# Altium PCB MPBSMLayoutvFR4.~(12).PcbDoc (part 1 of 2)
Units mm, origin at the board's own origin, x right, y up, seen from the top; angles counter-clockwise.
Board outline 131.7 x 110.39 mm, 4 copper layers (Top Layer, Power, GroundPlane, Bottom Layer), stack 2.286 mm thick; 156 components, 77 nets, 429 pads, 117 vias.
Unrouted connection lines stored in the file: 25.
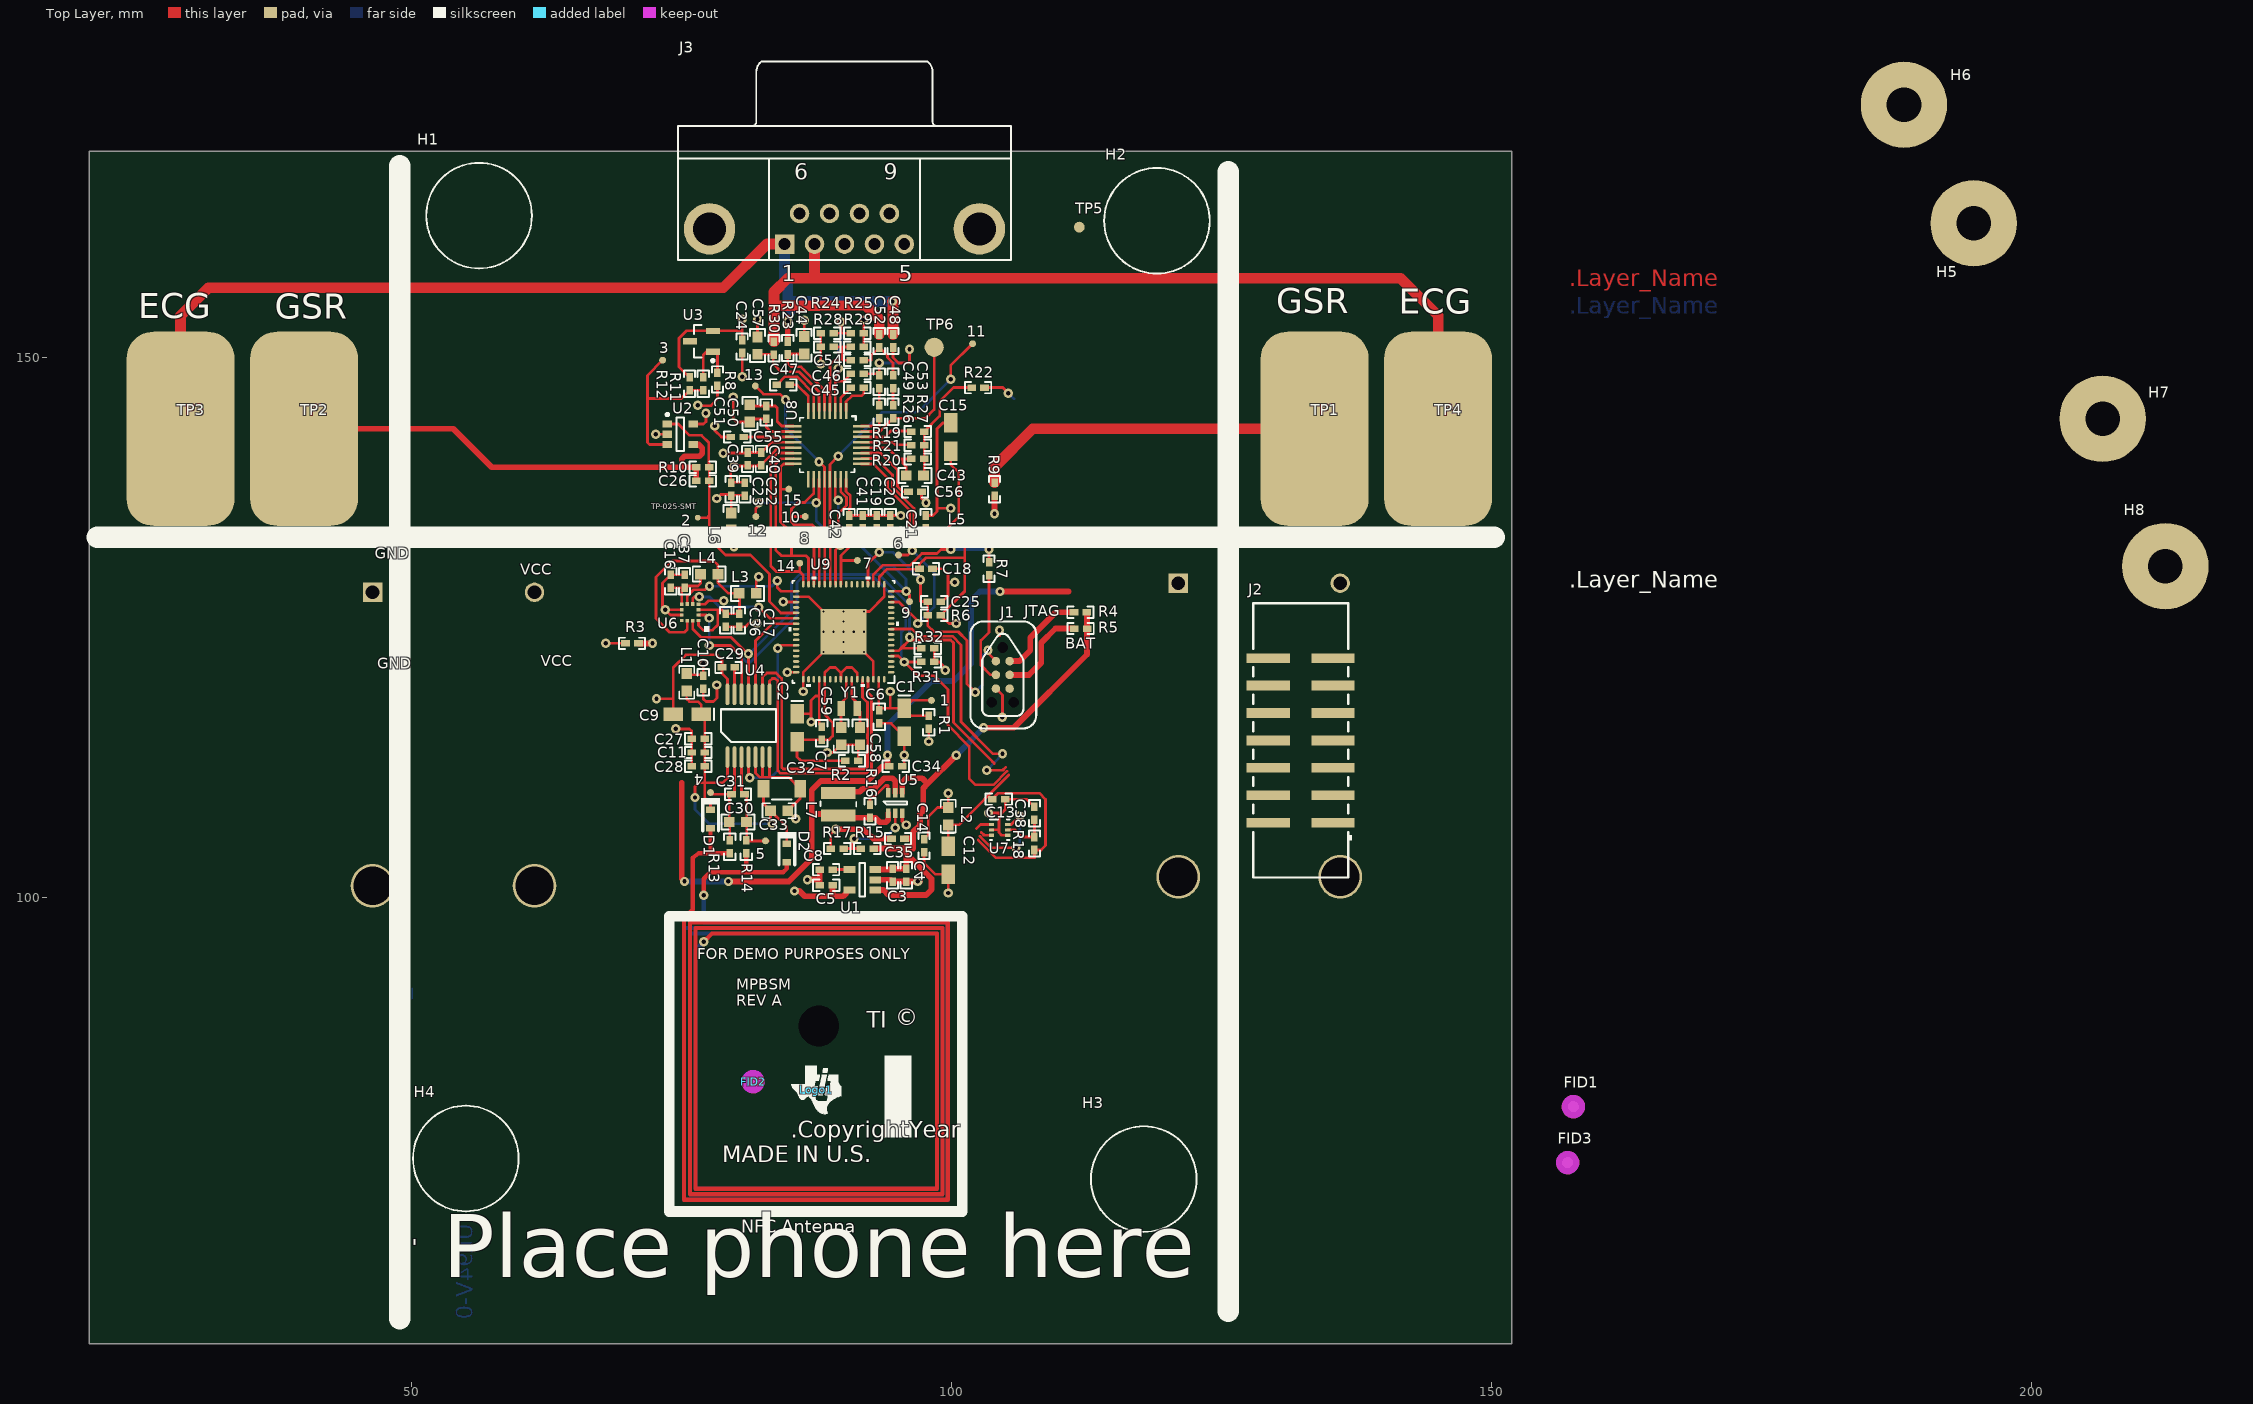
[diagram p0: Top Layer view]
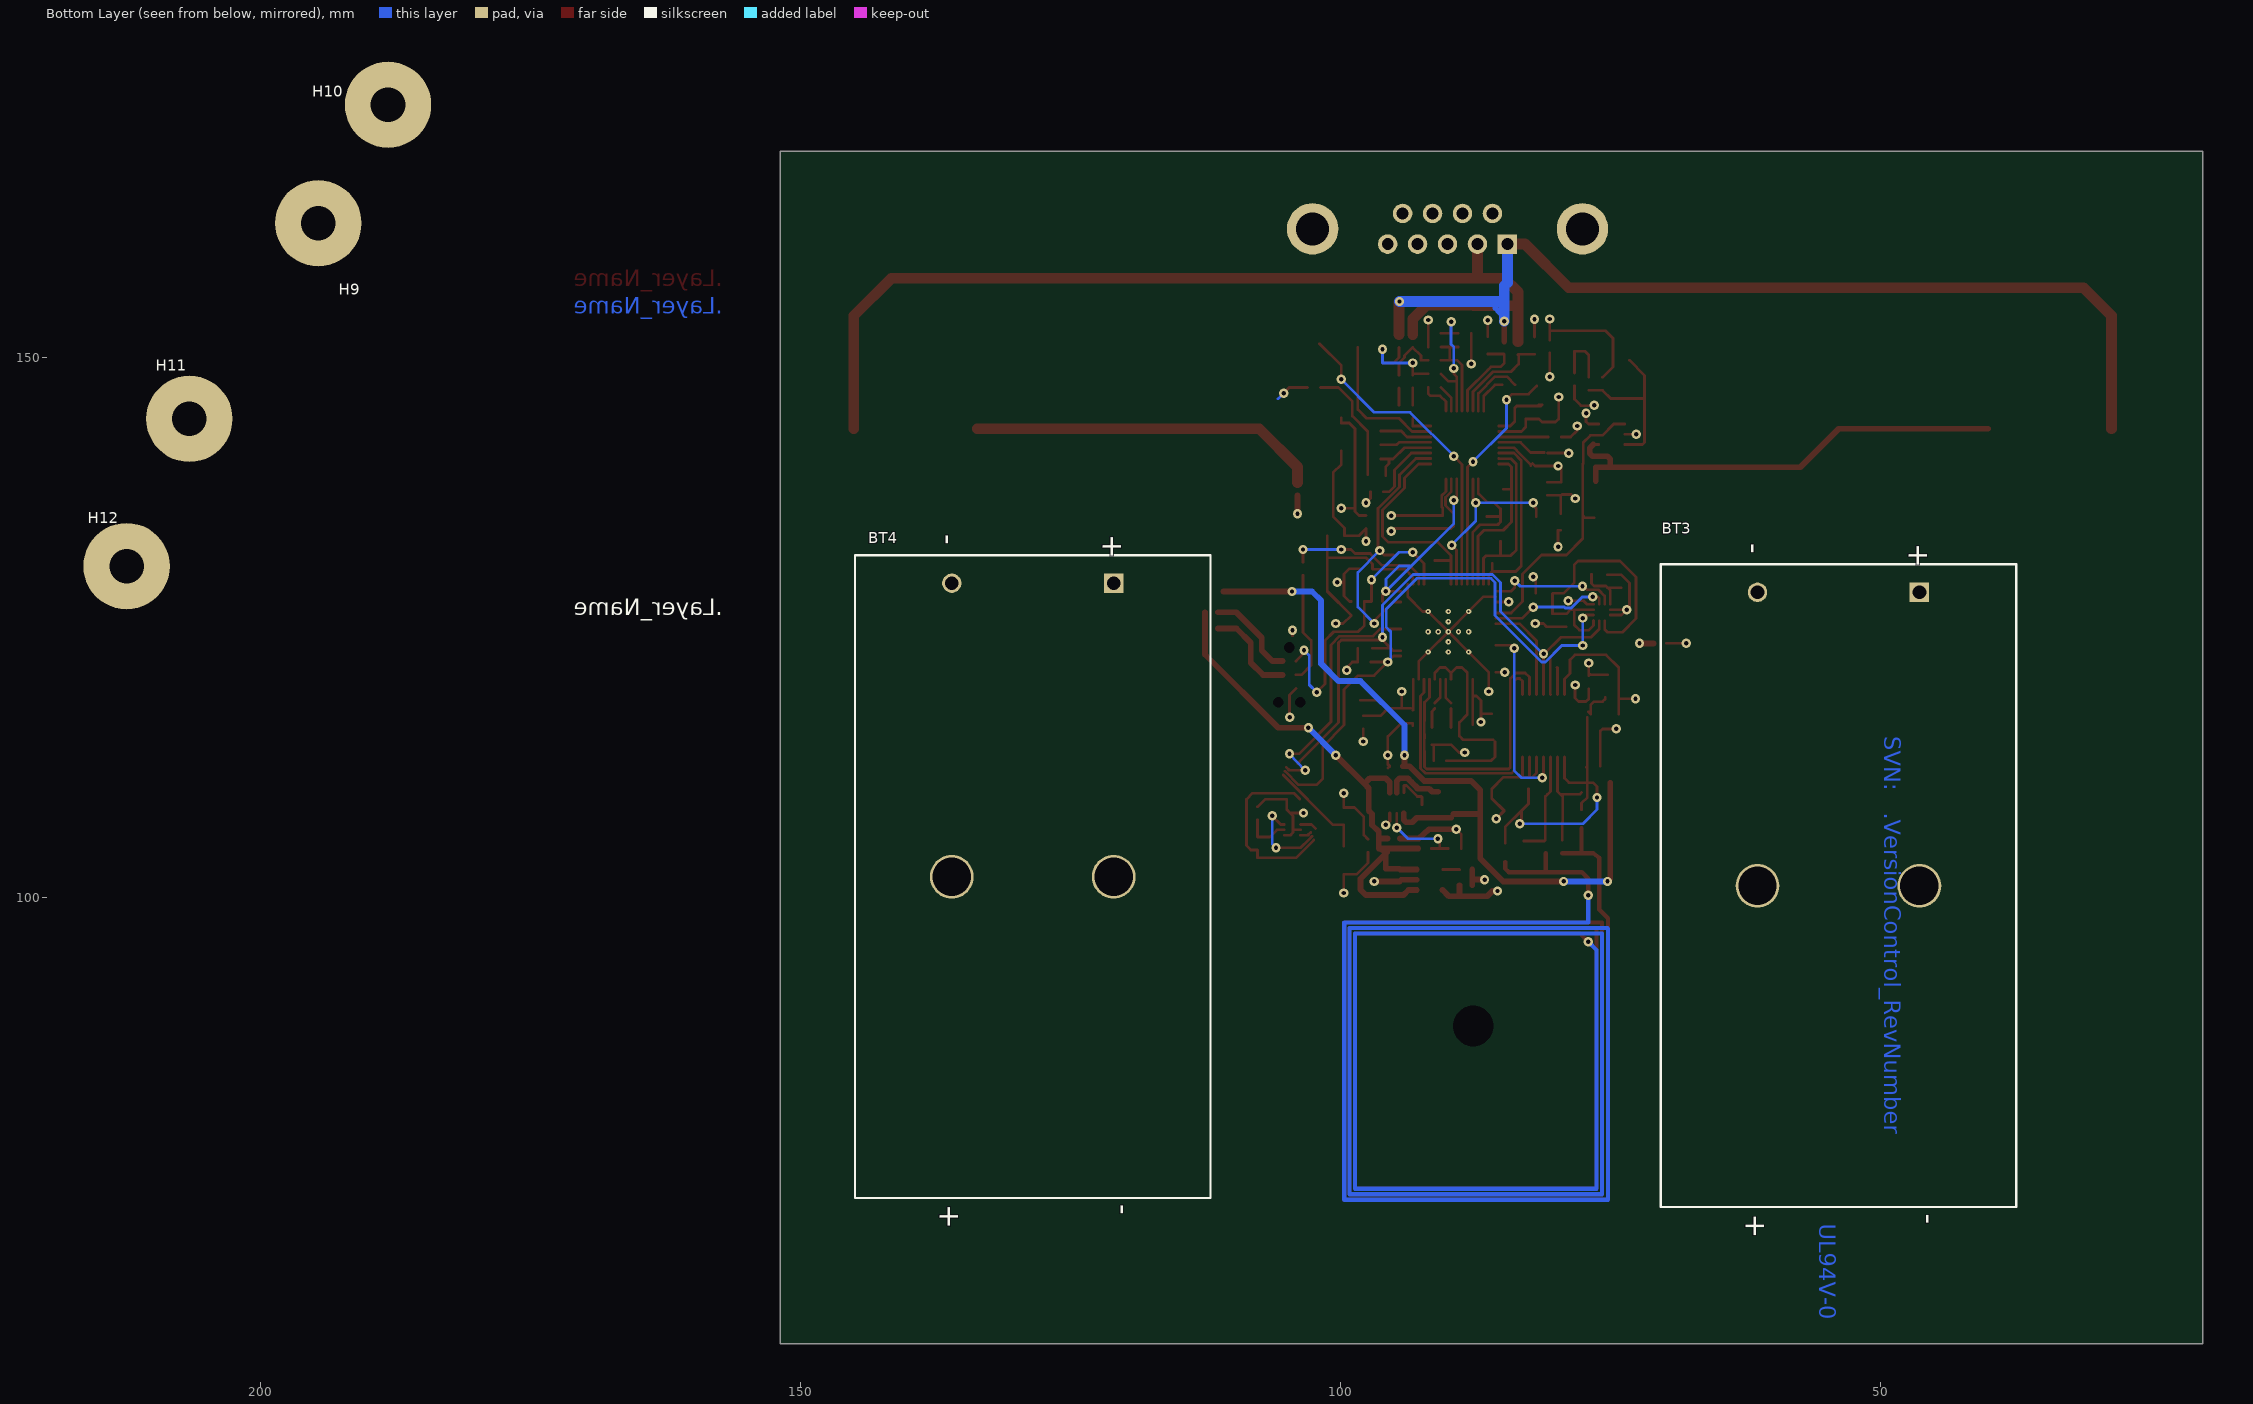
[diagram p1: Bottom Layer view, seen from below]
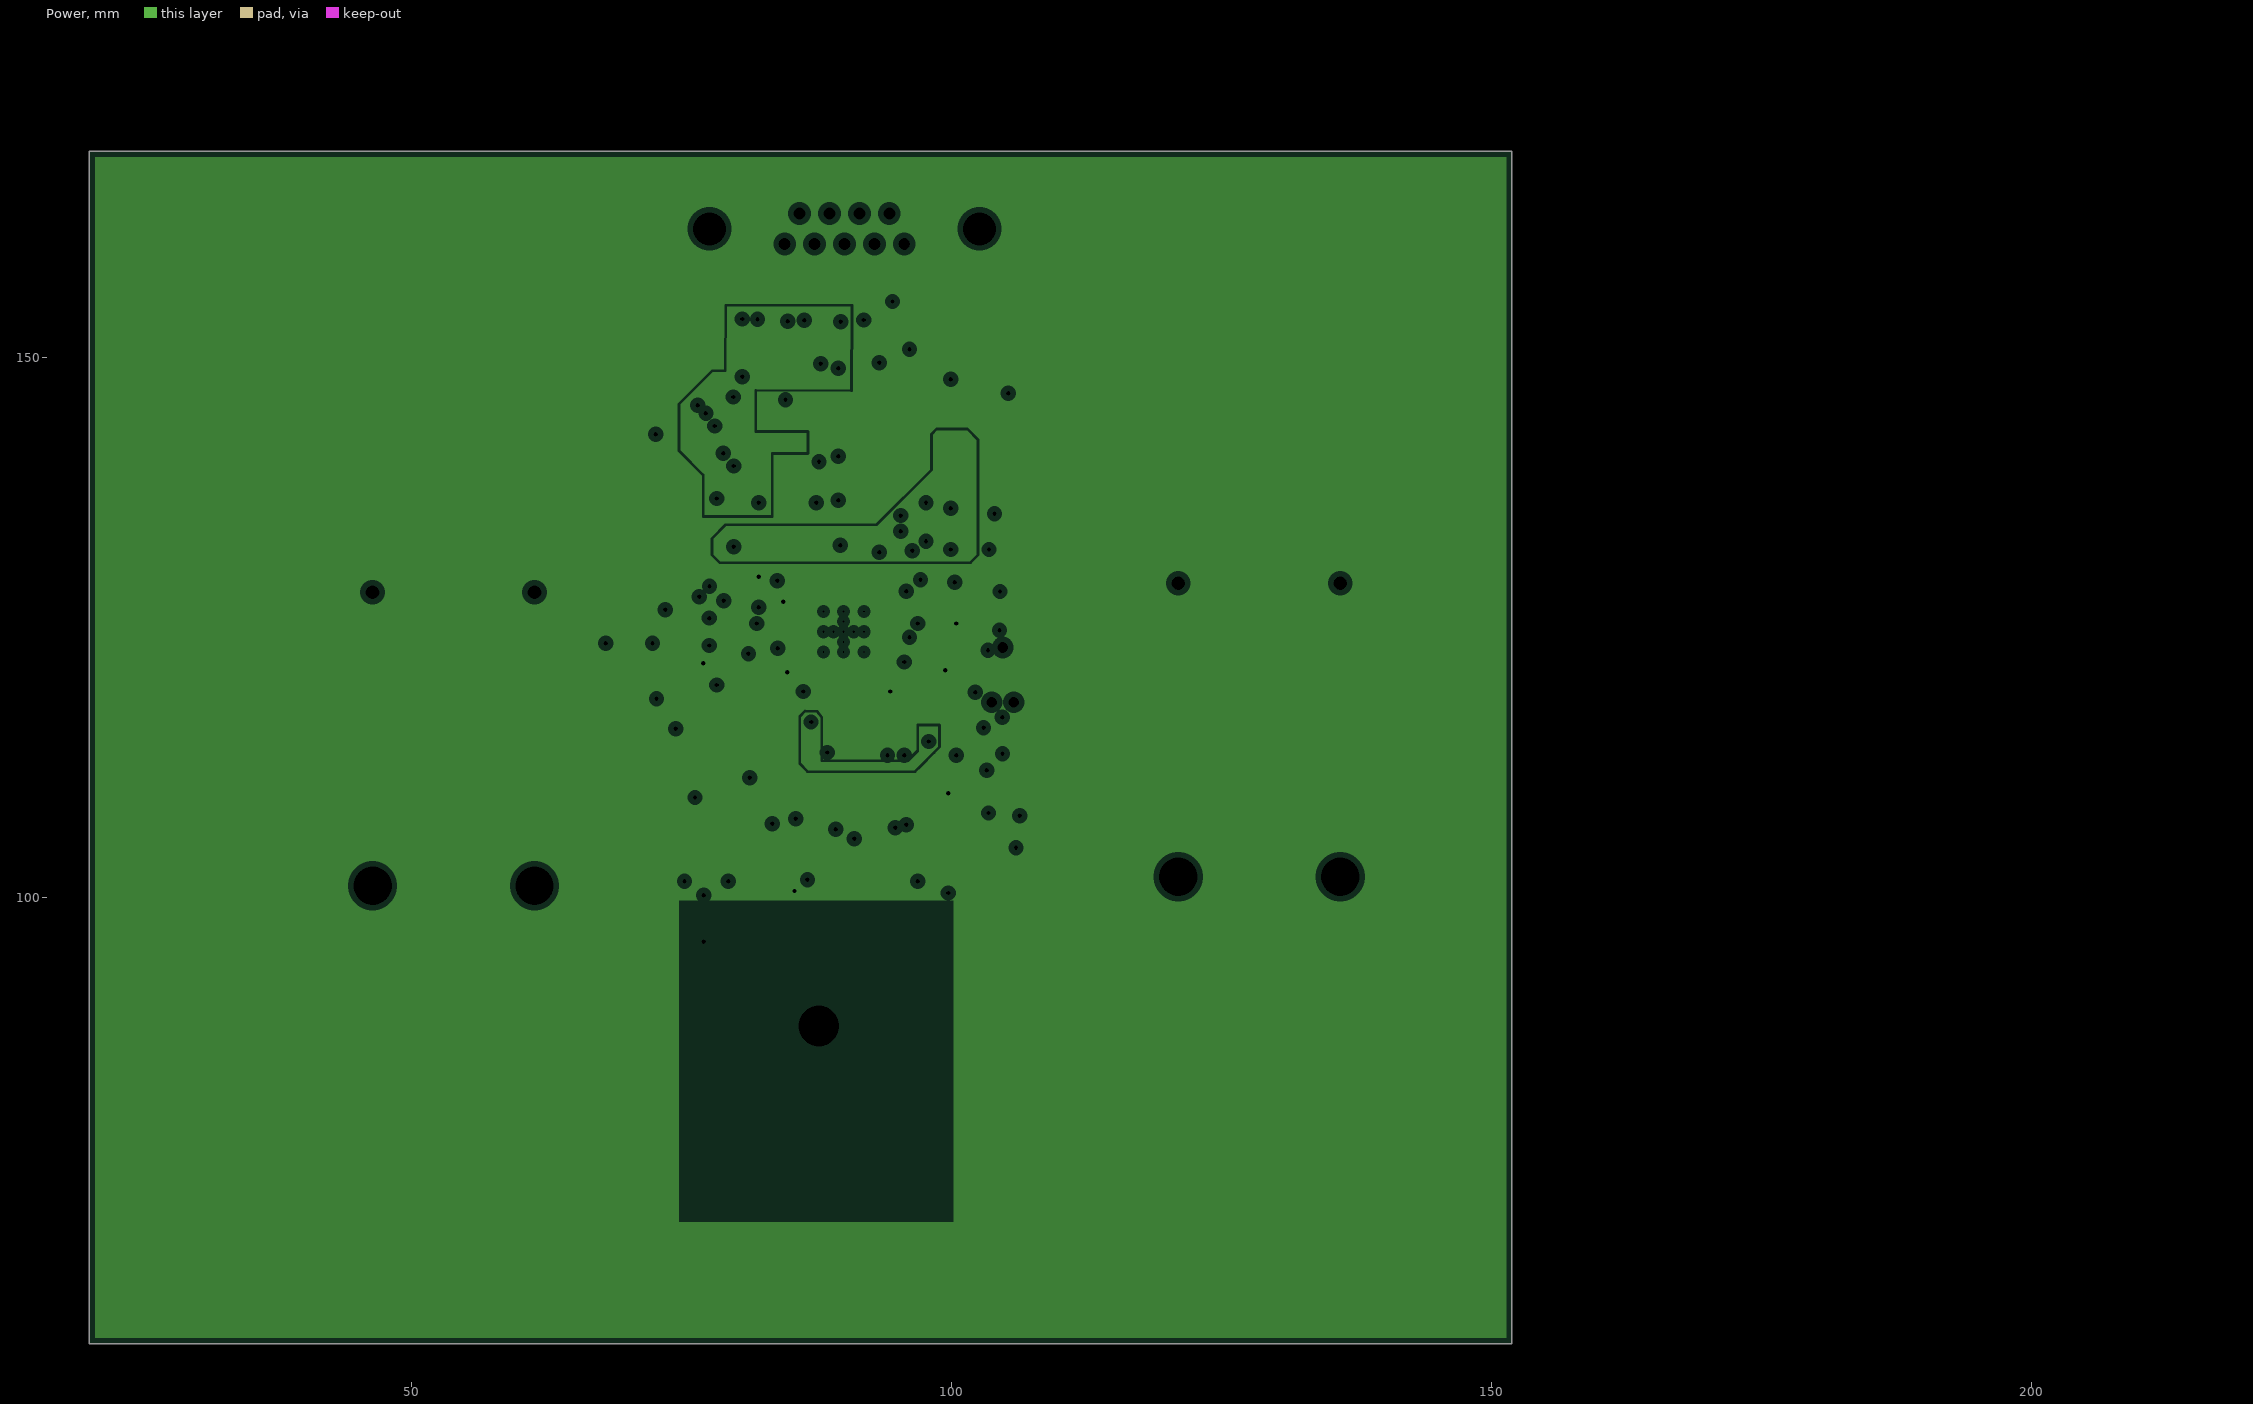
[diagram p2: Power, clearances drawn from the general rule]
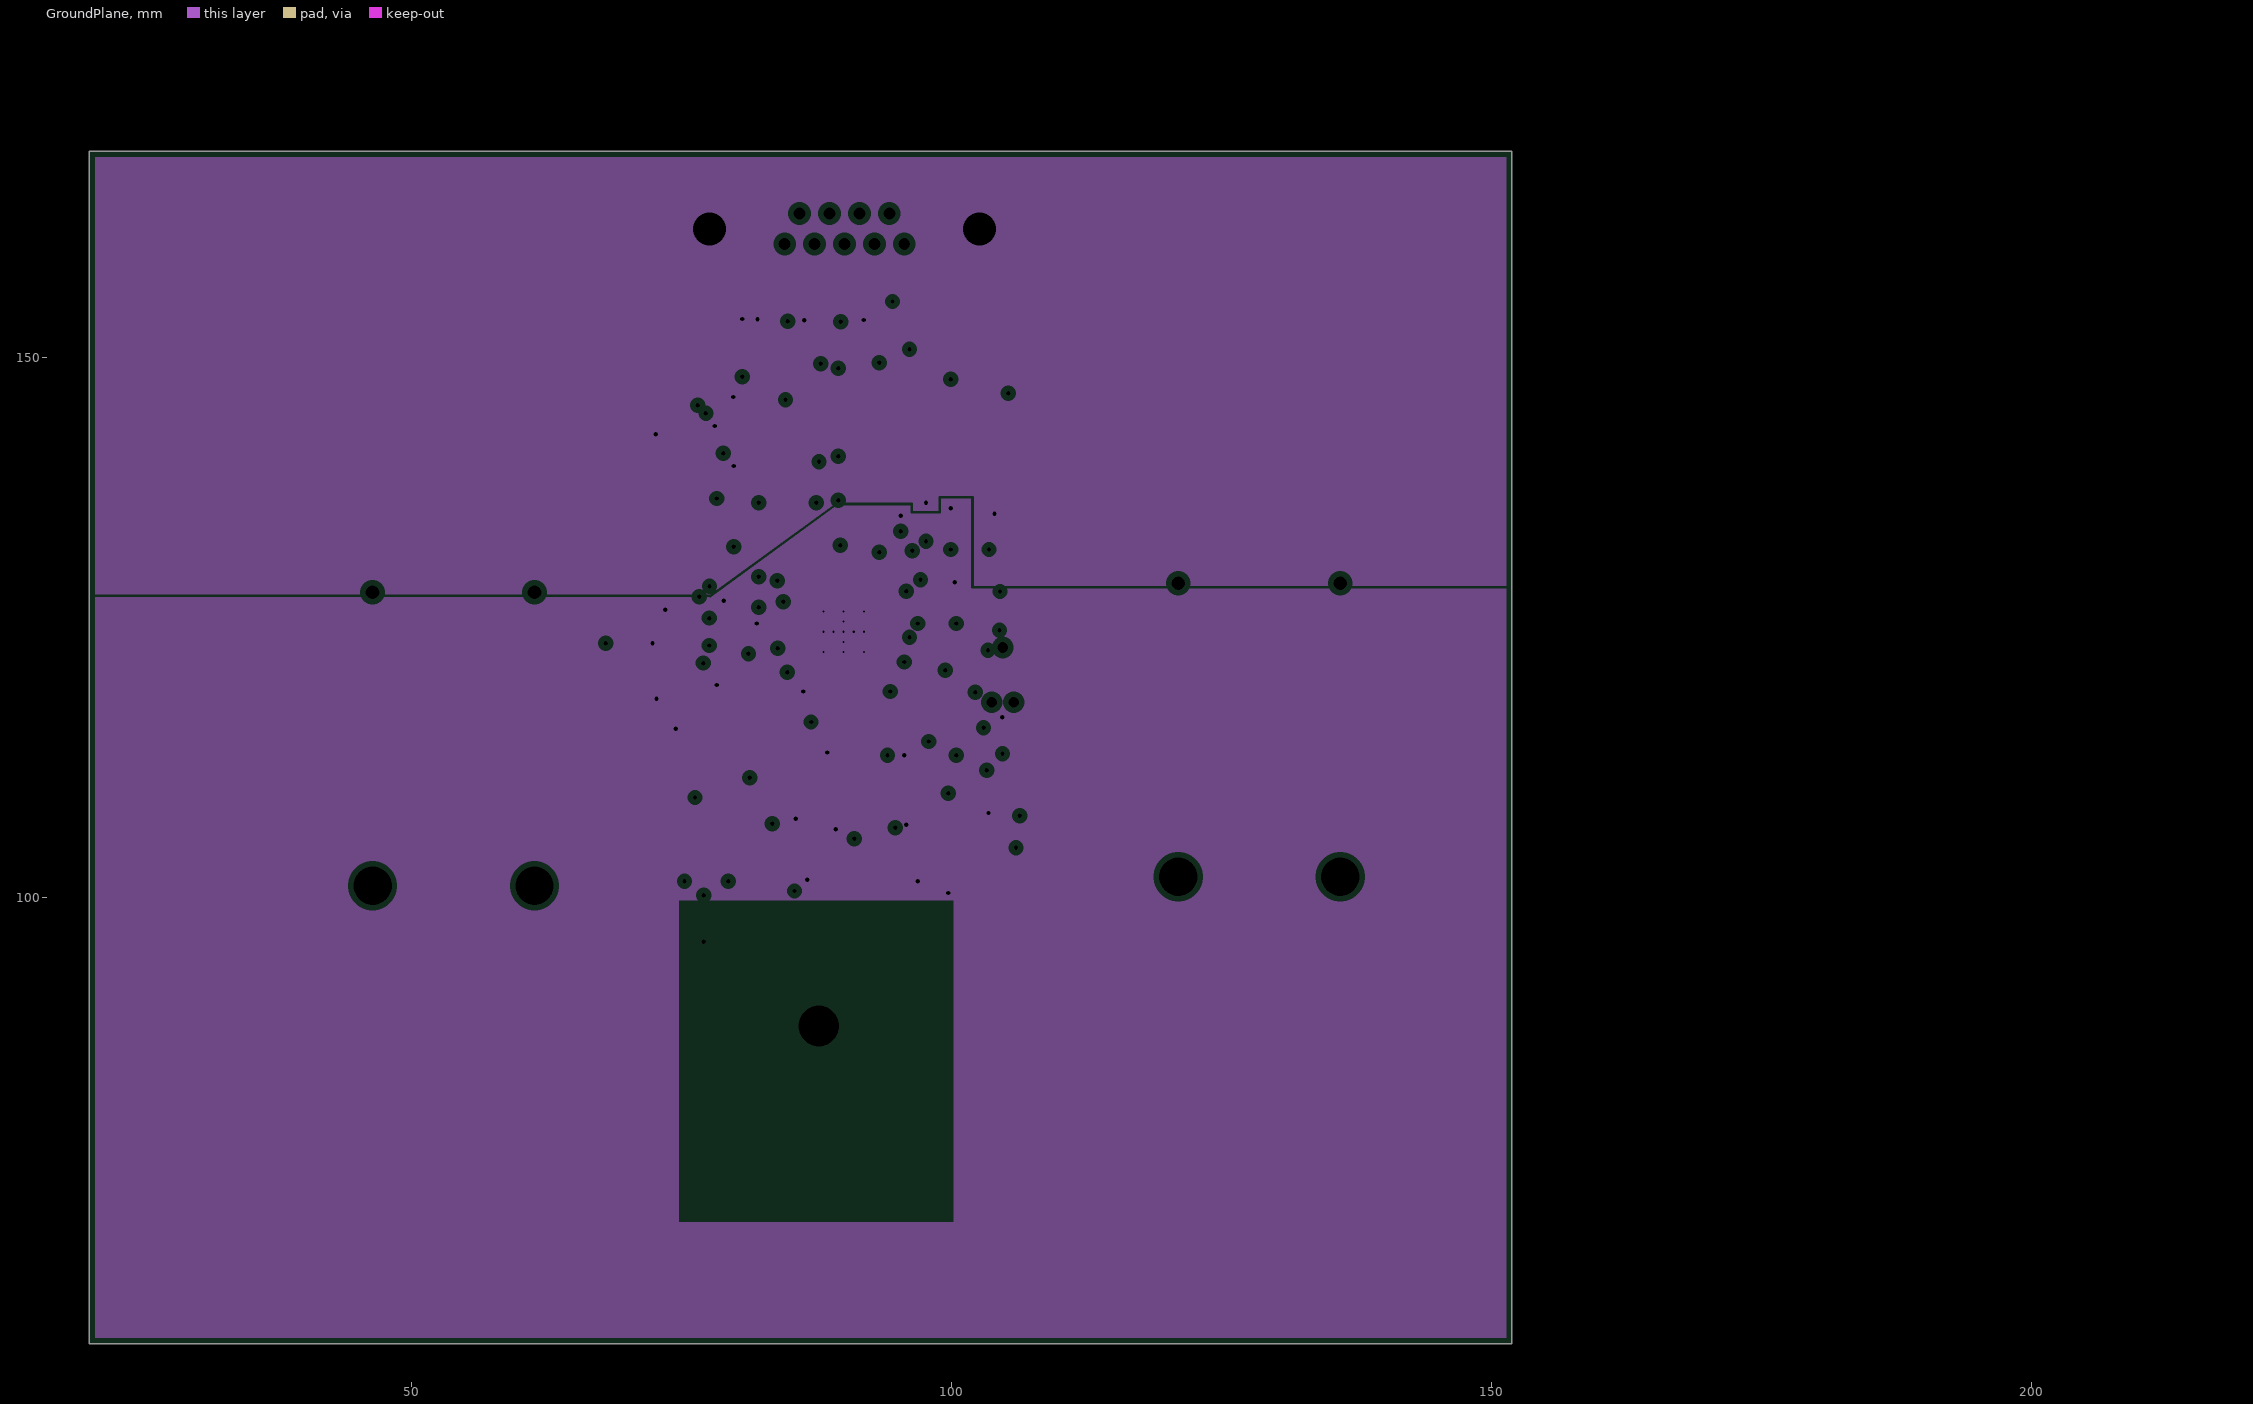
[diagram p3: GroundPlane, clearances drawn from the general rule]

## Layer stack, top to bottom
Top Solder: solder mask 0.0102, Solder Resist, Dk 3.5
Top Layer: signal copper 0.0356
Dielectric1: core 1.5037, FR-4, Dk 4.8
Power: plane copper 0.0356, net DVCC
Dielectric2: prepreg 0.32, FR-4, Dk 4.8
GroundPlane: plane copper 0.0356, net GND
Dielectric3: core 0.32, FR-4, Dk 4.8
Bottom Layer: signal copper 0.0356
Bottom Solder: solder mask 0.0102, Solder Resist, Dk 3.5

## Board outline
20.218,169.037 20.218,58.649 150.825,58.649 151.917,58.649 151.917,158.471 151.917,169.037 20.218,169.037

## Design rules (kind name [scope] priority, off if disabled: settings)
AcuteAngle [All] p1: minimum=4.50000000000000E+0001 checktracksonly=FALSE
AssemblyTestPointUsage [All] p1: valid=2
Clearance Clearance_BoardEdge_MountingHoles [OnCopper and InComponentClass('Mounting Holes') vs IsKeepOut] p1: gap=1.016
Clearance Clearance_BoardEdge_Poly [OnCopper and InPoly vs IsKeepOut] p2: gap=0.635
Clearance Clearance_BoardEdge [OnCopper and Not InComponentClass('Logo') and not InComponentClass('FiducialMark') and not InRegion(1000,500,4000,800) and Not IsKeepout vs IsKeepOut] p3: gap=1.905
Clearance Clearance_Poly [InPolygon] p4: gap=0.635
Clearance [All] p5: gap=0.1
ComponentClearance ComponentClearance_Shunt [InComponentClass('Header') vs InComponentClass('Shunt')] p1: gap=0 collisioncheckmode=3 verticalgap=0 showdistances=FALSE
ComponentClearance ComponentClearance_MountingHoles_FiducialMarks [InComponentClass('Mounting Holes') vs InComponentClass('FiducialMark')] p2: gap=1.27 collisioncheckmode=3 verticalgap=0.254 showdistances=FALSE
ComponentClearance ComponentClearance_Logo [InComponentClass('Logo')] p3: gap=1.27 collisioncheckmode=3 verticalgap=0.254 showdistances=FALSE
ComponentClearance ComponentClearance_ScrewToNut [(HasFootprint('NY PMS 440 0025 PH')) vs (HasFootprint('Keystone_1902C'))] p4: gap=0.127 collisioncheckmode=3 verticalgap=0.254 showdistances=FALSE
ComponentClearance ComponentClearance_MountingHoles [InComponentClass('Mounting Holes')] p5: gap=6.35 collisioncheckmode=3 verticalgap=2540 showdistances=FALSE
ComponentClearance ComponentClearance_SmallPassives [HasFootprint('0201*') or HasFootprint('0402*') or HasFootprint('0508') or HasFootprint('0603*') or HasFootprint('0612') or HasFootprint('0805*') or HasFootprint('0815*') or HasFootprint('0830*') or HasFootprint('1206*') or HasFootprint('1210*') or HasFootprint('1808*') or HasFootprint('1812*') or HasFootprint('1825*') or HasFootprint('2010*') or HasFootprint('2220*') or HasFootprint('2225*') or HasFootprint('2512*') or HasFootprint('2728*') or HasFootprint('3518*') vs HasFootprint('0201*') or HasFootprint('0402*') or HasFootprint('0508') or HasFootprint('0603*') or HasFootprint('0612') or HasFootprint('0805*') or HasFootprint('0815*') or HasFootprint('0830*') or HasFootprint('1206*') or HasFootprint('1210*') or HasFootprint('1808*') or HasFootprint('1812*') or HasFootprint('1825*') or HasFootprint('2010*') or HasFootprint('2220*') or HasFootprint('2225*') or HasFootprint('2512*') or HasFootprint('2728*') or HasFootprint('3518*')] p6: gap=0.508 collisioncheckmode=3 verticalgap=0.254 showdistances=FALSE
ComponentClearance ComponentClearance_THtoSMT [IsThruComponent vs IsSMTComponent] p7: gap=2.54 collisioncheckmode=3 verticalgap=0.762 showdistances=FALSE
ComponentClearance ComponentClearance_THtoTH [IsThruComponent vs IsThruComponent] p8: gap=3 collisioncheckmode=3 verticalgap=0.762 showdistances=FALSE
ComponentClearance [All] p9: gap=1.016 collisioncheckmode=3 verticalgap=0.254 showdistances=FALSE
DiffPairsRouting [All] p1: maxlimit=2.54 minlimit=0.254 mostfreqgap=0.254 toplayer_minwidth=0.381 toplayer_maxwidth=0.381 toplayer_prefwidth=0.381 bottomlayer_minwidth=0.381 bottomlayer_maxwidth=0.381 bottomlayer_prefwidth=0.381 maxuncoupledlength=25.4
FabricationTestPointUsage TestPointUsage [All] p1: valid=2 allowmultiple=FALSE
FabricationTestpoint Testpoint [All] p1: side=3 testpointundercomponent=TRUE minsize=1.016 maxsize=2.54 preferedsize=1.524 minholesize=0 maxholesize=1.016 preferedholesize=0.813 testpointgrid=0.025 allowsidetop=TRUE allowsidebottom=TRUE usegrid=TRUE gridtolerance=0
FanoutControl Fanout_LCC [IsLCC] p1: bgadir=Out bgaviamode=Centered fanoutstyle=Auto fanoutdirection=Alternating viagrid=0.025 // Fanout_LCC (Default Rule)
FanoutControl Fanout_BGA [IsBGA] p2: bgadir=Out bgaviamode=Centered fanoutstyle=Auto fanoutdirection=Alternating viagrid=0.025 // Fanout_BGA (Default Rule)
FanoutControl Fanout_Default [All] p4: bgadir=Out bgaviamode=Centered fanoutstyle=Auto fanoutdirection=Alternating viagrid=0.025 // Fanout_Default (Default Rule)
FanoutControl Fanout_Small [(CompPinCount < 5)] p5: bgadir=Out bgaviamode=Centered fanoutstyle=Auto fanoutdirection=OutThenIn viagrid=0.025 // Fanout_Small (Default Rule)
Height [All] p1: minheight=0 maxheight=55.4 prefheight=12.7
HoleSize [All] p1: absolutevalues=TRUE maxlimit=6.375 minlimit=0.1 maxpercent=80.000 minpercent=20.000
MinimumAnnularRing MinimumAnnularRing_ThermalPadVias [IsVia and InAnyComponent] p1: minimumring=0.15
MinimumAnnularRing [All] p2: minimumring=0.229
MinimumSolderMaskSliver MinimumSolderMaskSliver_Logo [InComponentClass('Logo') vs InComponentClass('Logo')] p1: minsoldermaskwidth=0.018
MinimumSolderMaskSliver [All] p2: minsoldermaskwidth=0.08
PlaneClearance [All] p1: clearance=0.508
PlaneConnect [All] p1: planeconnectstyle=Relief reliefexpansion=0.254 reliefentries=4 reliefconductorwidth=0.254 reliefairgap=0.254
PolygonConnect [All] p1: connectstyle=Relief reliefconductorwidth=0.254 reliefentries=4 polygonreliefangle="90 Angle" airgapwidth=0.254
RoutingVias ThermalPadVias [IsVia and InAnyComponent] p1: holewidth=0.2 width=0.5 viastyle="Through Hole" minholewidth=0.2 minwidth=0.5 maxholewidth=0.33 maxwidth=0.6
RoutingVias [All] p2: holewidth=0.406 width=0.864 viastyle="Through Hole" minholewidth=0.2 minwidth=0.66 maxholewidth=1.016 maxwidth=1.651
SMDToCorner [All] p1: distance=30000
SilkToSilkClearance SilkToSilkClearance_Pb-FreeLogo [(HasFootprint('Pb-Free_Overlay_Medium') OR HasFootprint('Pb-Free_Overlay_Small')) vs (HasFootprint('Pb-Free_Overlay_Medium') OR HasFootprint('Pb-Free_Overlay_Small'))] p1: silktosilkclearance=0
SilkToSilkClearance [All] p2: silktosilkclearance=0
SilkToSolderMaskClearance SilkscreenOverComponentPads [IsPad] p1: minsilkscreentomaskgap=0.127 clearancetoexposedcopper=TRUE
SolderMaskExpansion [All] p1: expansion=0.05
Width [All] p1: maxlimit=2.54 minlimit=0.152 preferedwidth=0.254 checkconnectedcopper=TRUE
14 further rules are at their usual default settings.

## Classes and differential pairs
component class Logo: Logo1
component class Designator: FID1 FID2 FID3 H1 H2 H3 H4 H5 H6 H7 H8 H9 H10 H11 H12 Logo1 ZZ1 ZZ2 ZZ3 ZZ4
component class FiducialMark: FID1 FID2 FID3
component class AssemblyNote: ZZ1 ZZ2 ZZ3 ZZ4
component class Battery: BT3 BT4 U?
component class BMA280: C36 C37 U6
component class "Boost Converter": C34 C35 L7 R15 R16 R17 U5
component class ECG: 6 7 8 9 10 11 12 13 14 15 C39 C40 C41 C42 C43 C44 C45 C46 C47 C48 C49 C50 C51 C52 C53 C54 C55 C56 C57 R19 R20 R21 R22 R23 R24 R25 R26 R27 R28 R29 R30 TP6 U8
component class GSR: 2 3 C26 R8 R9 R10 R11 R12 U2 U3
component class "JTAG SPY-BY-WIRE": C25 J1 J2 R4 R5 R6 R7
component class MSP430FR5XXX: C58 C59 R31 R32 U9 Y1
component class "Power Filtering": 1 C1 C2 C3 C4 C5 C6 C7 C8 C9 C10 C11 C12 C13 C14 C15 C16 C17 C18 C19 C20 C21 C22 C23 C24 L1 L2 L3 L4 L5 L6 R1 R2 R3 U1
component class Temperature: C38 R18 U7
component class Transponder: 4 5 C27 C28 C29 C30 C31 C32 C33 D1 D2 R13 R14 U4
component class "Analog Connector": J3
component class "Mounting Holes": H5 H6 H7 H8

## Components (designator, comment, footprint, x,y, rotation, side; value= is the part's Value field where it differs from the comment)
1 "TP-025-SMT" TP_25MIL-SMT#1 98.171,118.212 r90 top
2 "TP-025-SMT" TP_25MIL-SMT#2 76.53,135.128 r0 top
3 "TP-025-SMT" TP_25MIL-SMT#1 73.279,149.708 r0 top
4 "TP-025-SMT" TP_25MIL-SMT#1 77.72,109.676 r0 top
5 "TP-025-SMT" TP_25MIL-SMT#1 82.804,105.207 r270 top
6 "TP-025-SMT" TP_25MIL-SMT#1 95.123,131.674 r0 top
7 "TP-025-SMT" TP_25MIL-SMT#1 91.313,131.166 r0 top
8 "TP-025-SMT" TP_25MIL-SMT#1 85.217,133.198 r0 top
9 "TP-025-SMT" TP_25MIL-SMT#1 96.139,127.356 r0 top
10 "TP-025-SMT" TP_25MIL-SMT#1 86.487,135.23 r0 top
11 "TP-025-SMT" TP_25MIL-SMT#1 101.981,151.232 r0 top
12 "TP-025-SMT" TP_25MIL-SMT#1 81.915,135.23 r0 top
13 "TP-025-SMT" TP_25MIL-SMT#1 81.864,147.32 r0 top
14 "TP-025-SMT" TP_25MIL-SMT#1 85.979,130.912 r90 top
15 "TP-025-SMT" TP_25MIL-SMT#1 84.963,137.77 r0 top
BT3 "2462" Keystone_2462 53.924,114.63 r270 bottom
BT4 "2462" Keystone_2462 128.524,115.468 r270 bottom
C1 "293D106X9010A2TE3" 3216-18 95.631,116.18 r270 top
C2 "293D106X9010A2TE3" 3216-18 85.725,115.672 r270 top
C3 "C1005X5R1A104K" 0402 94.569,102.028 r270 top
C4 "C1005X5R0J105M" 0402 95.839,102.028 r270 top
C5 "C1005X5R1C225K050BC" 0402 88.422,101.092 r180 top
C6 "C1005X5R1A104K" 0402 93.345,116.688 r270 top
C7 "C1005X5R1A104K" 0402 88.011,115.164 r270 top
C8 "C1005X7R1E103K" 0402 88.417,102.54 r180 top
C9 "293D105X9016A2TE3" 3216-18 75.565,116.942 r180 top
C10 "C1005X5R1A104K" 0402 77.038,119.888 r270 top
C11 "C1005X5R1A104K" 0402 76.581,113.386 r180 top
C12 "293D106X9010A2TE3" 3216-18 99.728,103.422 r270 top
C13 "C1005X5R1A104K" 0402 104.404,109.068 r0 top
C14 "C1005X5R1A104K" 0402 97.487,104.75 r270 top
C15 "293D105X9016A2TE3" 3216-18 99.949,142.596 r90 top
C16 "CL05A106MQ5NUNC" 0402 74.041,129.247 r90 top
C17 "CL05A106MQ5NUNC" 0402 80.391,125.624 r270 top
C18 "C1005X5R1A104K" 0402 97.663,130.404 r0 top
C19 "C1005X5R1A104K" 0402 93.091,134.722 r90 top
C20 "C1005X5R1C225K050BC" 0402 94.361,134.722 r90 top
C21 "CL05A106MQ5NUNC" 0402 97.663,134.722 r90 top
C22 "CL05A106MQ5NUNC" 0402 80.899,137.77 r90 top
C23 "C1005X5R1A104K" 0402 79.629,137.77 r90 top
C24 "C1005X5R1A104K" 0402 80.645,150.978 r90 top
C25 "C1005X8R1H222K" 0402 98.425,127.356 r0 top
C26 "C1005X7R1E103K" 0402 76.997,138.532 r180 top
C27 "C1005X5R0J105M" 0402 76.581,114.656 r180 top
C28 "C1005X5R1A104K" 0402 76.581,112.116 r180 top
C29 "GRM155R60J474KE19D" 0402 79.375,121.26 r0 top
C30 "C1608C0G1H330J" 0603 80.26,106.941 r0 top
C31 "GRM1555C1H390JA01D" 0402 80.26,109.515 r0 top
C32 "C3216X5R1A107M160AC" 1206_190 84.324,110.023 r0 top
C33 "Used in BOM report" 0603 84.07,107.991 r0 top
C34 "CL05A106MQ5NUNC" 0402 94.869,112.116 r0 top
C35 "CL05A106MQ5NUNC" 0402 95.072,105.41 r180 top
C36 "C1005X5R1A104K" 0402 79.121,125.624 r270 top
C37 "C1005X5R1A104K" 0402 75.311,129.247 r90 top
C38 "C1005X7R1E103K" 0402 107.706,107.752 r90 top
C39 "C1005X5R1C105K050BC" 0402 81.153,140.564 r270 top
C40 "C1005X5R1A104K" 0402 82.423,140.564 r270 top
C41 "C1005X5R1C105K050BC" 0402 91.821,134.722 r90 top
C42 "C1005X5R1A104K" 0402 90.551,134.722 r90 top
C43 "C0603C152K5RACTU" 0603 96.647,139.04 r180 top
C44 "GRM1885C1H302JA01D" 0603 86.385,151.091 r90 top
C45 "GRM155R61A472KA01D" 0402 91.313,147.168 r0 top
C46 "C1005X8R1H222K" 0402 91.313,148.438 r0 top
C47 "GRM155R61A472KA01D" 0402 84.455,147.422 r180 top
C48 "C1005X5R1A104K" 0402 94.615,151.486 r270 top
C49 "C1005X8R1H222K" 0402 93.345,147.722 r90 top
C50 "C1005X5R1A104K" 0402 82.88,144.872 r270 top
C51 "C1608X5R0J106M" 0603 81.356,144.78 r270 top
C52 "C1005X5R1A104K" 0402 93.345,151.486 r270 top
C53 "C1005X8R1H222K" 0402 94.615,147.722 r90 top
C54 "C1005X8R1H222K" 0402 91.313,149.708 r0 top
C55 "C1005X5R1C105K050BC" 0402 80.183,142.596 r180 top
C56 "C1005X5R1C105K050BC" 0402 96.647,137.516 r0 top
C57 "GRM1885C1H302JA01D" 0603 82.063,151.063 r90 top
C58 "06035A100JAT2A" 0603 91.567,114.91 r270 top
C59 "06035A100JAT2A" 0603 89.814,114.91 r270 top
D1 "CDBU0130L" SOD-523F 77.72,107.229 r270 top
D2 "CDBU0130L" SOD-523F 84.785,104.089 r270 top
FID1 "Fiducial" Fiducial10-20 157.607,80.594 r0 top
FID2 "Fiducial" Fiducial10-20 81.661,82.906 r0 top
FID3 "Fiducial" Fiducial10-20 157.074,75.413 r0 top
H1 "SJ61A2" Bumpon_SJ61A2 56.286,163.093 r0 top
H2 "SJ61A2" Bumpon_SJ61A2 119.05,162.611 r0 top
H3 "SJ61A2" Bumpon_SJ61A2 117.831,73.889 r0 top
H4 "SJ61A2" Bumpon_SJ61A2 55.067,75.794 r0 top
H5 "NY PMS 440 0025 PH" "NY PMS 440 0025 PH" 194.666,162.382 r90 top
H6 "NY PMS 440 0025 PH" "NY PMS 440 0025 PH" 188.214,173.355 r90 top
H7 "NY PMS 440 0025 PH" "NY PMS 440 0025 PH" 206.604,144.272 r90 top
H8 "NY PMS 440 0025 PH" "NY PMS 440 0025 PH" 212.421,130.638 r90 top
H9 "1902C" Keystone_1902C 194.665,162.376 r90 bottom
H10 "1902C" Keystone_1902C 188.239,173.33 r90 bottom
H11 "1902C" Keystone_1902C 206.604,144.272 r90 bottom
H12 "1902C" Keystone_1902C 212.42,130.632 r180 bottom
J1 "TC2030-MCP-NL" TC2030-MCP-NL 104.775,120.574 r180 top
J2 "61201420621" Wurth_61201420621 132.359,114.503 r180 top
J3 "182-009-213R171" NORCOMP_182-009-213R171 90.119,171.374 r0 top
L1 "BLM18HG601SN1D" 0603 75.514,119.888 r270 top
L2 "BLM18HG601SN1D" 0603 99.728,107.486 r270 top
L3 "BLM18HG601SN1D" 0603 81.153,128.118 r180 top
L4 "BLM18HG601SN1D" 0603 77.597,129.896 r0 top
L5 "BLM18HG601SN1D" 0603 100.457,133.452 r180 top
L6 "BLM18HG601SN1D" 0603 79.629,134.772 r90 top
L7 "EPL3015-472MLB" EPL3015 89.56,108.61 r90 top
Logo1 "Texas Instruments" TI_Symbol_Overlay_Small 87.503,82.144 r0 top
R1 "ERJ-2GE0R00X" 0402 97.917,116.18 r270 top
R2 "ERJ-2GE0R00X" 0402 90.805,112.624 r180 top
R3 "ERJ-2GE0R00X" 0402 70.444,123.489 r180 top
R4 "ERJ-2GE0R00X" 0402 111.963,126.365 r0 top
R5 "ERJ-2GE0R00X" 0402 111.982,124.861 r0 top
R6 "CRCW040247K0JNED" 0402 98.425,126.086 r0 top
R7 "ERJ-2GE0R00X" 0402 103.505,130.404 r90 top
R8 "CRCW040221K5FKED" 0402 78.359,147.93 r270 top
R9 "CRCW040210K0FKED" 0402 104.013,137.77 r90 top
R10 "ERJ-2RKF1004X" 0402 76.997,139.802 r0 top
R11 "CRCW040211K8FKED" 0402 77.044,147.517 r90 top
R12 "CRCW04028K06FKED" 0402 75.774,147.517 r270 top
R13 "ERJ-2GE0R00X" 0402 79.498,104.655 r270 top
R14 "ERJ-2GE0R00X" 0402 81.022,104.655 r270 top
R15 "ERJ-2RKF1004X" 0402 92.237,104.496 r0 top
R16 "ERJ-2GE0R00X" 0402 92.481,107.95 r90 top
R17 "ERJ-2RKF2003X" 0402 89.443,104.496 r0 top
R18 "CRCW04024K99FKED" 0402 107.706,104.958 r270 top
R19 "ERJ-2GE0R00X" 0402 96.901,143.104 r0 top
R20 "ERJ-2RKF1004X" 0402 96.901,140.564 r0 top
R21 "ERJ-2RKF1003X" 0402 96.901,141.834 r0 top
R22 "ERJ-2RKF1003X" 0402 102.489,147.168 r0 top
R23 "CRCW040251K1FKED" 0402 84.861,150.837 r270 top
R24 "CRCW040210M0FKED" 0402 88.519,152.202 r180 top
R25 "CRCW040210M0FKED" 0402 91.313,152.202 r180 top
R26 "CRCW040240K2FKED" 0402 93.345,144.928 r270 top
R27 "CRCW040240K2FKED" 0402 94.615,144.928 r270 top
R28 "CRCW040210M0FKED" 0402 88.519,150.932 r180 top
R29 "CRCW040210M0FKED" 0402 91.313,150.932 r180 top
R30 "CRCW040251K1FKED" 0402 83.587,150.809 r270 top
R31 "CRCW04023K30JNED" 0402 97.825,121.768 r180 top
R32 "CRCW04023K30JNED" 0402 97.825,123.038 r180 top
TP1 "TESTPOINT" TP_SM_1MM#1 133.655,143.358 r0 top
TP2 "TESTPOINT" TP_SM_1MM#2 40.081,143.358 r90 top
TP3 "TESTPOINT" TP_SM_1MM#2 28.651,143.358 r90 top
TP4 "TESTPOINT" TP_SM_1MM#2 145.085,143.358 r90 top
TP5 "TESTPOINT" TP_SM_1MM#3 111.862,162.027 r90 top
TP6 "Pogo Pad" PogoPad 98.425,150.901 r0 top locked
U1 "TPS73030DBVR" DBV0005A_N 91.77,101.6 r180 top
U2 "LMP2231AMFE" MF05A_L 74.919,142.85 r0 top
U3 "LM4041AIM3-1.2" MF03A_N 76.886,151.46 r180 top
U4 "RF430CL331HCPW" PW0014A_M 81.236,115.864 r90 top
U5 "TPS61220DCK" DCK0006A_N 94.818,108.712 r90 top
U6 "BMA280" LGA-12P 75.819,126.361 r90 top
U7 "TMP112AIDRL" DRL0006A 104.478,106.221 r0 top
U8 "ADS1292RIPBS" PBS0032A_N 88.519,141.853 r270 top
U9 "MSP430FR5889IRGCR" RGC0064B 90.043,124.562 r180 top
Y1 "FC-12M 32.7680KA-A3" Epson_FC-12M 90.551,117.45 r0 top
ZZ1 "This Assembly Note is for PCB labels only" AssemblyNoteLabel 35.992,195.631 r0 top
ZZ2 "These assemblies are ESD sensitive, ESD precautions shall be observed." AssemblyNote 35.992,192.865 r0 top
ZZ3 "These assemblies must be clean and free from flux and all contaminants. Use of no clean flux is not acceptable." AssemblyNote 35.992,190.616 r0 top
ZZ4 "These assemblies must comply with workmanship standards IPC-A-610 Class 2, unless otherwise specified." AssemblyNote 35.992,188.366 r0 top

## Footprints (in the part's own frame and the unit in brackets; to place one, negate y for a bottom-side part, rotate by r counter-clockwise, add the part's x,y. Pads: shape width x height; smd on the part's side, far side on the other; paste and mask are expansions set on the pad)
0402 [mm] "0402 from SM-752 data"
  rect 0.8x0.6 smd: 1(-0.6,0) 2(0.6,0)
  silkscreen extent -1.22,-0.52 1.22,0.52, body extent -0.55,-0.3 0.55,0.3, height 0.6
0603 [mm] "0603 from SM-752 data"
  rect 1x0.95 smd: 1(-0.8,0) 2(0.8,0)
  silkscreen extent -1.52,-0.69 1.52,0.69, body extent -0.87,-0.47 0.87,0.47, height 0.85
1206_190 [mm] "1206_190"
  rect 1.1x1.6 smd: 1(-1.7,0) 2(1.7,0)
  silkscreen extent -0.9,-1 0.9,1, body extent -1.75,-0.95 1.75,0.95, height 1.9
3216-18 [mm] "Medium density IPC, based on Kemet T495 dimensions"
  rect 1.8x1.25 smd: 1(-1.3,0) 2(1.3,0)
  silkscreen extent -2.49,-0.54 -2.49,0.54, body extent -1.7,-0.9 1.7,0.9, height 1.8
AssemblyNote [mm] "Assembly Note"
AssemblyNoteLabel [mm] "Assembly Note for PCB Labels"
Bumpon_SJ61A2 [mil] "3M Hemispherical Bumpon transparent"
  round 1 on Mech3: 0(0,0)
  silkscreen extent -192,-192 192,192, body extent -191,-192 193,192, height 250
DBV0005A_N [mm] "SOT23, 5-Leads, Body 2.9x1.6mm, Pitch 0.95mm, Lead Span 2.8mm, IPC Medium Density"
  rect 1.1x0.65 smd: 1(-1.2,0.95) 2(-1.2,0) 3(-1.2,-0.95) 4(1.2,-0.95) 5(1.2,0.95)
  silkscreen extent -0.25,-1.55 0.25,1.55, body extent -1.42,-1.46 1.42,1.46, height 1.08
DCK0006A_N [mm] "SOT23, 6-Leads, Body 2x1.3mm, Pitch 0.65mm, Lead Span 2.1mm, IPC Medium Density"
  rect 0.85x0.4 smd: 1(-0.95,0.65) 2(-0.95,0) 3(-0.95,-0.65) 4(0.95,-0.65) 5(0.95,0) 6(0.95,0.65)
  silkscreen extent -0.15,-1.1 0.15,1.1, body extent -1.14,-1 1.14,1, height 0.94
DRL0006A [mm] "SOTFL, 6-Flat Leads, Body 1.2x1.6x0.6mm, Pitch 0.5mm, TI recommended"
  rect 0.5x0.3 smd: 1(-0.75,0.5) 2(-0.75,0) 3(-0.75,-0.5) 4(0.75,-0.5) 5(0.75,0) 6(0.75,0.5)
  silkscreen extent -0.9,-0.95 0.9,0.95, body extent -0.85,-0.85 0.85,0.85, height 0.62
EPL3015 [mm] "COILCRAFT"
  rect 1.12x3.2 smd: 1(-1.04,0) 2(1.04,0)
  silkscreen extent -0.22,-1.65 0.23,1.68, body extent -1.6,-1.6 1.6,1.6, height 1.55
Epson_FC-12M [mm] "Epson"
  rect 0.7x1.4 smd: 1(-0.75,0) 2(0.75,0)
  body extent -1.05,-0.63 1.05,0.63, height 0.6
Fiducial10-20 [mm]
  round 1 smd mask+0.5: 1(0,0)
  Top Layer keep-out circle w1.178: c0,0 r0.5
Keystone_1902C [mil] "Hex Standoff, 4-40 threaded, nylon"
  round 1 on Mech4: 0(0,0)
  body extent -145,-126 146,126, height 501
Keystone_2462 [mm] "2x AA Battery Holder, Through-hole mount"
  rect 1.8x1.8 hole 1.27: 1(-13.59,7.495)
  round 1.8 hole 1.27: 2(-13.59,-7.495)
  round 4.05 hole 3.55: 3(13.59,-7.495) 4(13.59,7.495)
  silkscreen extent -16.18,-16.46 43.33,16.46, body extent -16.31,-16.46 43.4,16.46, height 16
LGA-12P [mm]
  rect 0.3x0.35 smd mask+0.05: 1(-0.75,-0.775) 2(-0.25,-0.775) 3(0.25,-0.775) 4(0.75,-0.775) 7(0.75,0.775) 8(0.25,0.775) 9(-0.25,0.775) 10(-0.75,0.775)
  rect 0.35x0.3 smd mask+0.05: 5(0.775,-0.25) 6(0.775,0.25) 11(-0.775,0.25) 12(-0.775,-0.25)
  silkscreen extent -1.8,-1.8 -1.29,-1.3
MF03A_N [mm] "SOT23, 3-Leads, Body 2.9x1.3mm, Pitch 0.95mm, Lead Span 2.4mm, IPC Medium Density"
  rect 1.3x0.6 smd: 1(-1.05,0.95) 2(-1.05,-0.95) 3(1.05,0)
  silkscreen extent -1.18,-1.5 0.7,1.92, body extent -0.7,-1.5 0.7,1.5, height 1.12
MF05A_L [mm] "SOT23, 5-Leads, Body 2.9x1.6mm, Pitch 0.95mm, Lead Span 2.8mm, IPC High Density"
  rect 0.9x0.65 smd: 1(-1.2,0.95) 2(-1.2,0) 3(-1.2,-0.95) 4(1.2,-0.95) 5(1.2,0.95)
  silkscreen extent -1.32,-1.55 0.35,1.95, body extent -0.9,-1.55 0.9,1.55, height 1.19
NORCOMP_182-009-213R171 [mm] "Connector; D Subminiature 9 Position; Right Angle"
  rect 1.8x1.8 hole 1.092: 1(-5.54,-10.92)
  round 1.8 hole 1.092: 2(-2.77,-10.92) 3(0,-10.92) 4(2.77,-10.92) 5(5.54,-10.92) 6(-4.155,-8.08) 7(-1.385,-8.08) 8(1.385,-8.08) 9(4.155,-8.08)
  round 4.76 hole 3.05: 10(-12.495,-9.5) 11(12.495,-9.5)
  silkscreen extent -15.4,-12.4 15.4,6, body extent -15.41,-12.98 15.41,6.1, height 12.55
"NY PMS 440 0025 PH" [mm] "4-40 nylon screw and mounting hole"
  round 8 hole 3.2: 1(0,0)
  body extent -3.3,-3.3 3.3,3.3, height 2.69
PBS0032A_N [mil]
  rect 60x9 smd: 1(-124,68.9) 2(-124,49.21) 3(-124,29.53) 4(-124,9.84) 5(-124,-9.84) 6(-124,-29.53) 7(-124,-49.21) 8(-124,-68.9) 17(124,-68.9) 18(124,-49.21) 19(124,-29.53) 20(124,-9.84) 21(124,9.84) 22(124,29.53) 23(124,49.21) 24(124,68.9)
  rect 9x60 smd: 9(-68.9,-124) 10(-49.21,-124) 11(-29.53,-124) 12(-9.84,-124) 13(9.84,-124) 14(29.53,-124) 15(49.21,-124) 16(68.9,-124) 25(68.9,124) 26(49.21,124) 27(29.53,124) 28(9.84,124) 29(-9.84,124) 30(-29.53,124) 31(-49.21,124) 32(-68.9,124)
  silkscreen extent -104,-100 100,104, body extent -140,-140 140,140, height 48
PogoPad [mil] "No Solder Paste"
  round 70 smd paste-35: 1(0,0)
PW0014A_M [mm] "TSOP, 14-Leads, Body 5x4.4mm, Pitch 0.65mm, IPC Low Density"
  oval 2x0.35 smd: 1(-2.9,1.95) 2(-2.9,1.3) 3(-2.9,0.65) 4(-2.9,0) 5(-2.9,-0.65) 6(-2.9,-1.3) 7(-2.9,-1.95) 8(2.9,-1.95) 9(2.9,-1.3) 10(2.9,-0.65) 11(2.9,0) 12(2.9,0.65) 13(2.9,1.3) 14(2.9,1.95)
  silkscreen extent -1.5,-2.55 1.53,2.55, body extent -3.21,-2.5 3.21,2.5, height 0.98
RGC0064B [mm]
  oval 0.6x0.24 smd mask+0.07: 1(-4.4,3.75) 2(-4.4,3.25) 3(-4.4,2.75) 4(-4.4,2.25) 5(-4.4,1.75) 6(-4.4,1.25) 7(-4.4,0.75) 8(-4.4,0.25) 9(-4.4,-0.25) 10(-4.4,-0.75) 11(-4.4,-1.25) 12(-4.4,-1.75) 13(-4.4,-2.25) 14(-4.4,-2.75) 15(-4.4,-3.25) 16(-4.4,-3.75) 33(4.4,-3.75) 34(4.4,-3.25) 35(4.4,-2.75) 36(4.4,-2.25) 37(4.4,-1.75) 38(4.4,-1.25) 39(4.4,-0.75) 40(4.4,-0.25) 41(4.4,0.25) 42(4.4,0.75) 43(4.4,1.25) 44(4.4,1.75) 45(4.4,2.25) 46(4.4,2.75) 47(4.4,3.25) 48(4.4,3.75)
  oval 0.24x0.6 smd mask+0.07: 17(-3.751,-4.4) 18(-3.251,-4.4) 19(-2.751,-4.4) 20(-2.251,-4.4) 21(-1.75,-4.4) 22(-1.25,-4.4) 23(-0.75,-4.4) 24(-0.25,-4.4) 25(0.25,-4.4) 26(0.75,-4.4) 27(1.25,-4.4) 28(1.75,-4.4) 29(2.251,-4.4) 30(2.751,-4.4) 31(3.251,-4.4) 32(3.751,-4.4) 49(3.751,4.4) 50(3.251,4.4) 51(2.751,4.4) 52(2.251,4.4) 53(1.75,4.4) 54(1.25,4.4) 55(0.75,4.4) 56(0.25,4.4) 57(-0.25,4.4) 58(-0.75,4.4) 59(-1.25,4.4) 60(-1.75,4.4) 61(-2.251,4.4) 62(-2.751,4.4) 63(-3.251,4.4) 64(-3.751,4.4)
  rect 4.25x4.25 smd paste-2.112: 65(0,0)
  silkscreen extent -5.1,-5.1 5.1,5.1, body extent -4.57,-4.57 4.57,4.57, height 1.01
SOD-523F [mm] "COMCHIP"
  rect 0.6x0.8 smd paste-0.05: 1(-0.85,0) 2(0.85,0)
  silkscreen extent -1.92,-0.87 1.1,0.88, body extent -0.9,-0.5 0.9,0.5, height 0.85
TC2030-MCP-NL [mil] "TAG-CONNECT"
  round 31 smd paste-16: 1(-25,-50) 2(25,-50) 3(-25,0) 4(25,0) 5(-25,50) 6(25,50)
  round 25 hole 39 unplated: MH1(0,-100) MH2(-40,100) MH3(40,100)
  silkscreen extent -122,-195 118,195
TI_Symbol_Overlay_Small [mm]
  silkscreen extent -2.3,-2.23 2.3,2.24
TP_25MIL-SMT#1 [mm]
  round 0.635 smd mask-0.064: 1(0,0)
TP_25MIL-SMT#2 [mm]
  round 0.535 smd mask-0.064: 1(0,0)
TP_SM_1MM#1 [mm] "1mm Test Point, SMT"
  rrect50% 10x18 smd paste-0.5: 1(0,0)
TP_SM_1MM#2 [mm] "1mm Test Point, SMT"
  rrect50% 18x10 smd paste-0.5: 1(0,0)
TP_SM_1MM#3 [mm] "1mm Test Point, SMT"
  round 1 smd paste-0.5: 1(0,0)
Wurth_61201420621 [mm] "Header, 2.54mm, 7x2, SMT"
  rect 4x0.9 smd: 1(-3,7.62) 2(3,7.62) 3(-3,5.08) 4(3,5.08) 5(-3,2.54) 6(3,2.54) 7(-3,0) 8(3,0) 9(-3,-2.54) 10(3,-2.54) 11(-3,-5.08) 12(3,-5.08) 13(-3,-7.62) 14(3,-7.62)
  silkscreen extent -4.75,-12.7 4.4,12.7, body extent -4.75,-12.7 4.75,12.7, height 10.43

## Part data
1 2 3 4 5 6 7 8 9 10 11 12 13 14 15: "Test Point, O.025\""
BT3 BT4: "2x AA Battery Holder, Through-hole mount"
C1 C2 C12: "CAP, TA, 10 µF, 10 V, +/- 10%, 3.4 ohm, SMD"
C3 C6 C7 C10 C11 C13 C14 C18 C19 C23 C24 C28 C36 C37 C40 C42 C48 C50 C52: "CAP, CERM, 0.1 µF, 10 V, +/- 10%, X5R, 0402"
C4 C27: "CAP, CERM, 1 µF, 6.3 V, +/- 20%, X5R, 0402"
C5 C20: "CAP, CERM, 2.2 µF, 16 V, +/- 10%, X5R, 0402"
C8 C26 C38: "CAP, CERM, 0.01 µF, 25 V, +/- 10%, X7R, 0402"
C9 C15: "CAP, TA, 1 µF, 16 V, +/- 10%, 9.3 ohm, SMD"
C16 C17 C21 C22 C34 C35: "CAP, CERM, 10 µF, 6.3 V, +/- 20%, X5R, 0402"
C25 C46 C49 C53 C54: "CAP, CERM, 2200 pF, 50 V, +/- 10%, X8R, 0402"
C29: "CAP, CERM, 0.47 µF, 6.3 V, +/- 10%, X5R, 0402"
C30: "CAP, CERM, 33 pF, 50 V, +/- 5%, C0G/NP0, 0603"
C31: "CAP, CERM, 39pF, 50V, +/-5%, C0G/NP0, 0402"
C32: "CAP, CERM, 100 µF, 10 V, +/- 20%, X5R, 1206_190"
C33: library part Capacitor, "CAP, CERM, xxxF, xxV, [TempCo], xx%, [PackageReference]"
C39 C41 C55 C56: "CAP, CERM, 1 µF, 16 V, +/- 10%, X5R, 0402"
C43: "CAP, CERM, 1500 pF, 50 V, +/- 10%, X7R, 0603"
C44 C57: "CAP, CERM, 3000 pF, 50 V, +/- 5%, C0G/NP0, 0603"
C45 C47: "CAP, CERM, 4700 pF, 10 V, +/- 10%, X5R, 0402"
C51: "CAP, CERM, 10 µF, 6.3 V, +/- 20%, X5R, 0603"
C58 C59: "CAP, CERM, 10 pF, 50 V, +/- 5%, C0G/NP0, 0603"
D1 D2: "Diode, Schottky, 35V, 0.1A, SOD-523F"
FID1 FID2 FID3: "Fiducial mark.  There is nothing to buy or mount."
H1 H2 H3 H4: "Bumpon, Hemisphere, 0.375 X 0.235, Black"
H5 H6 H7 H8: "Machine Screw, Round, #4-40 x 1/4, Nylon, Philips panhead"
H9 H10 H11 H12: "Standoff, Hex, 0.5\"L #4-40 Nylon"
J1: "Footprint for TC2030-MCP-NL"
J2: "Header(Shrouded), 2.54mm, 7x2, Gold, Black, SMT"
J3: "CONN DB9 FEMALE R/A SOLDER TH"
L1 L2 L3 L4 L5 L6: "Ferrite Bead, 600 ohm @ 100MHz, 0.2A, 0603"
L7: "Inductor, Shielded, Ferrite, 4.7uH, 1.2A, 0.14 ohm, SMD"
Logo1: library part TI_Logo, "Texas Instrument Corporate Signature"
R1 R2 R3 R4 R5 R7 R13 R14 R16 R19: "RES, 0, 5%, 0.063 W, 0402"
R6: "RES, 47 k, 5%, 0.063 W, 0402"
R8: "RES, 21.5 k, 1%, 0.063 W, 0402"
R9: "RES, 10.0 k, 1%, 0.063 W, 0402"
R10 R15 R20: "RES, 1.00 M, 1%, 0.1 W, 0402"
R11: "RES, 11.8 k, 1%, 0.063 W, 0402"
R12: "RES, 8.06 k, 1%, 0.063 W, 0402"
R17: "RES, 200 k, 1%, 0.1 W, 0402"
R18: "RES, 4.99 k, 1%, 0.063 W, 0402"
R21 R22: "RES, 100 k, 1%, 0.1 W, 0402"
R23 R30: "RES, 51.1 k, 1%, 0.063 W, 0402"
R24 R25 R28 R29: "RES, 10.0 M, 1%, 0.063 W, 0402"
R26 R27: "RES, 40.2 k, 1%, 0.063 W, 0402"
R31 R32: "RES, 3.3 k, 5%, 0.063 W, 0402"
TP1 TP2 TP3 TP4 TP5: library part TP_SM_1MM, "1mm Test Point, SMT"
TP6: library part PogoPad, "Pad for Pogo Pin Connector"
U1: "Single Output High PSRR LDO, 200 mA, Fixed 3 V Output, 2.7 to 5.5 V Input, 5-pin SOT-23 (DBV), -40 to 85 degC, Green (RoHS & no Sb/Br)"
U2: "Single Micropower Precision Op Amp"
U3: "Precision Micropower Shunt Voltage Reference, 3-pin SOT-23"
U4: library part RF430CL331H, "The Texas Instruments Dynamic NFC Interface Transponder RF430CL331H is an NFC Tag Type 4 device  that combines a wireless NFC interface and a wired SPI or I2C interface to connect the device to a host."
U5: "LOW INPUT VOLTAGE STEP-UP CONVERTER IN 6 PIN SC-70 PACKAGE, DCK0006A"
U6: library part BMA250, "14 bit, digital, triaxial acceleration sensor with intelligent on-chip motion triggered interrupt controller"
U7: "High-Accuracy, Low-Power, Digital Temperature Sensor With SMBus(TM)/Two-Wire Serial Interface, DRL0006A"
U8: "Low-Power, 2-Channel, 24-Bit Analog Front-End for Biopotential Measurement, PBS0032A"
U9: "Mixed-Signal Microcontrollers, RGC0064B"
Y1: "Crystal, 32.768kHz, 12.5pF, SMD"
ZZ1: library part AssemblyNoteLabel
ZZ2 ZZ3 ZZ4: library part AssemblyNote

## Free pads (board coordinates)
  round 0 hole 3.762 unplated: 0(87.732,88.062)

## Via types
v1: diameter 0.864, hole 0.406, Top Layer to Bottom Layer, 104 vias
v2: diameter 0.5, hole 0.2, Top Layer to Bottom Layer, 13 vias

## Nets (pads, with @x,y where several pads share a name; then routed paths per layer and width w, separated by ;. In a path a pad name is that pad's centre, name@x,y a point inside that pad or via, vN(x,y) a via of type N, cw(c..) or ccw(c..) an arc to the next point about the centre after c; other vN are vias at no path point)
3V: C3.1 C4.1 C35.1 R4.2 R5.2 R15.2 U1.1 U1.3 U5.4 | length 53.6
  Top Layer w0.254: U1.3@92.97,102.55 U1.3@93.048,102.628 ; 94.209,100.178 94.31,100.178 ; C3.1@94.491,102.55 C3.1@94.569,102.628 ; 96.485,106.02 96.485,106.061
  Top Layer w0.54: R15.2@92.837,104.496 96.485,104.496 ; U1.1@92.97,100.65 93.736,100.65 94.209,100.178 ; U1.3@92.97,102.55 C3.1@94.491,102.55 ; 94.31,100.178 97.663,100.178 98.171,100.686 98.171,101.702 95.723,104.15 96.485,104.496 ; C3.1@94.569,102.628 C4.1@95.839,102.628 95.839,104.034 ; U5.4@95.468,109.662 95.468,110.632 95.834,110.998 97.307,110.998 97.815,110.49 ; C35.1@95.672,105.41 96.485,105.41 ; 96.485,106.02 96.485,105.41 ; 96.485,106.061 97.104,106.68 97.104,107.696 97.409,108.001 97.409,110.084 97.815,110.49 ; v1(100.457,113.132) 97.815,110.49 ; v1(102.997,115.672) 105.791,115.672 112.582,122.463 R5.2@112.582,124.816 ; R4.2@112.563,126.365 112.582,126.346 R5.2@112.582,124.861 ; 96.485,104.496 96.485,105.41
  Bottom Layer w0.54: v1(100.457,113.132) v1(102.997,115.672)
ADS1292_DRDY: 9.1 U8.22 U9.16 | length 19.6
  Top Layer w0.254: U8.22@89.269,138.704 89.269,137.039 89.535,136.773 v1(89.535,136.754) ; U9.16@94.443,128.312 v1(95.825,128.312) 96.139,127.998 9.1@96.139,127.356
  Bottom Layer w0.254: v1(89.535,136.754) 89.535,134.602 93.479,130.658 ; 93.479,130.658 v1(95.825,128.312) 95.825,129.448 94.615,130.658 93.479,130.658
ADS1292_ELA: C52.1 J3.2 R30.1 TP4.1 | length 93.4
  Top Layer w1: R30.1@83.587,151.409 83.587,154.733 ; J3.2@87.349,160.454 87.351,157.302 ; C52.1@93.345,152.086 93.345,153.518 92.075,154.788 83.587,154.733 ; TP4.1@145.085,143.358 145.085,153.822 141.605,157.302 88.519,157.302 84.861,157.302 83.587,156.028 83.587,154.733
ADS1292_ERA: C48.1 J3.1 R23.1 TP3.1 | length 92.4
  Top Layer w0.54: R23.1@84.861,151.437 v1@84.861,153.67
  Top Layer w1: TP3.1@28.651,143.358 28.651,153.822 31.242,156.413 78.892,156.413 82.933,160.454 J3.1@84.579,160.454 ; v1(94.564,155.143) 94.615,155.092 C48.1@94.615,152.086
  Bottom Layer w0.54: v1@84.861,153.67 85.674,154.534
  Bottom Layer w1: J3.1@84.579,160.454 84.579,156.873 84.861,156.591 84.861,153.67 v1(84.861,153.314) ; 85.065,155.143 v1(94.564,155.143)
ADS1292_GPIO1: 6.1 U8.26 U9.14 | length 24.5
  Top Layer w0.254: U8.26@91.669,140.603 93.051,140.603 94.566,139.089 94.566,137.976 96.55,135.992 ; U9.14@94.443,127.312 95.167,127.312 96.889,125.59 v1@96.889,125.336 ; 6.1@95.123,131.674 95.993,131.674 v1(96.4,132.08) 96.556,132.236 96.556,135.992
  Bottom Layer w0.254: v1(96.4,132.08) 98.425,130.055 98.425,126.848 v1(96.901,125.324)
ADS1292_GPIO2: 7.1 U8.25 U9.25 | length 20.5
  Top Layer w0.254: U9.25@89.793,128.962 89.793,129.729 ; 89.792,129.73 89.792,131.626 91.008,132.842 95.58,132.842 96.139,133.401 96.139,135.839 94.112,137.866 94.112,138.8 92.809,140.103 U8.25@91.669,140.103 ; 89.792,131.166 7.1@91.313,131.166
ADS1292_IN1N: C46.1 R24.1 R25.2 U8.3 | length 12.8
  Top Layer w0.254: R24.1@89.119,152.202 89.789,152.202 ; U8.3@89.269,145.003 89.269,148.184 89.535,148.45 v1(89.535,148.946) ; 89.344,147.753 90.028,147.753 C46.1@90.713,148.438 ; v1(89.789,153.264) 89.789,152.202 ; R25.2@90.713,152.202 89.789,152.202
  Bottom Layer w0.254: v1(89.535,148.946) 89.535,150.932 89.789,151.186 v1(89.789,153.264)
ADS1292_IN1P: C54.1 R28.1 R29.2 U8.4 | length 9.1
  Top Layer w0.254: U8.4@88.769,145.003 88.769,149.246 89.23,149.708 C54.1@90.713,149.708 ; R28.1@89.119,150.932 89.916,150.932 ; 89.916,149.835 89.916,150.932 ; R29.2@90.713,150.932 89.916,150.932
ADS1292_IN2N: C44.1 R23.2 U8.5 | length 8.7
  Top Layer w0.254: C44.1@86.385,150.291 84.915,150.291 R23.2@84.861,150.237 84.861,149.447 85.217,149.092 86.101,149.092 86.385,148.807 88.269,146.924 U8.5@88.269,145.003
ADS1292_IN2P: C57.1 R30.2 U8.6 | length 9.5
  Top Layer w0.254: C57.1@82.063,150.263 83.533,150.263 R30.2@83.587,150.209 ; R30.2@83.533,150.209 83.533,149.359 84.255,148.638 85.913,148.638 87.769,146.782 U8.6@87.769,145.003
ADS1292_MAIN_CLKSEL: 14.1 U8.14 U9.32 | length 17.1
  Top Layer w0.254: U8.14@85.369,141.103 83.959,141.103 83.293,140.437 83.293,130.658 83.801,130.15 85.979,130.15 ; 14.1@85.979,130.912 85.979,130.15 ; U9.32@86.292,128.962 86.292,129.837 85.979,130.15
ADS1292_RESET: 8.1 U8.15 U9.31 | length 16.9
  Top Layer w0.254: 8.1@85.217,132.944 85.217,131.597 ; U8.15@85.369,140.603 85.349,140.583 84.255,140.583 83.747,140.075 83.747,132.128 84.278,131.597 85.217,131.597 ; U9.31@86.792,128.962 86.792,131.368 86.564,131.597 85.217,131.597
ADS1292_RESP_MODP/IN3N: R26.2 U8.32 | length 2.4
  Top Layer w0.254: U8.32@91.669,143.603 93.337,143.603 93.345,143.612 R26.2@93.345,144.328
ADS1292_RESP_MODP/IN3P: R27.2 TP6.1 U8.31 | length 13.4
  Top Layer w0.254: U8.31@91.669,143.103 93.391,143.103 R27.2@94.615,144.328 97.617,144.328 98.425,145.136 TP6.1@98.425,150.901
ADS1292_RLD: J3.4 R22.2 TP5.1 | length 3.2
  Top Layer w0.254: R22.2@103.089,147.168 104.775,147.168 v1(105.283,146.66)
  Bottom Layer w0.254: v1(105.283,146.66) 105.816,146.126
ADS1292_SPI_CS: 10.1 U8.18 U9.29 | length 14.1
  Top Layer w0.254: 85.309,135.23 10.1@86.487,135.23 ; 87.223,137.328 86.436,136.541 85.817,136.541 85.217,135.941 85.217,134.722 85.471,134.468 87.096,134.468 87.792,133.771 U9.29@87.792,128.962 ; 87.269,137.374 U8.18@87.269,138.704
ADS1292_SPI_DIN: 12.1 U8.19 U9.26 | length 17.3
  Top Layer w0.254: 12.1@81.915,135.23 81.915,135.992 82.169,136.246 v1(82.169,136.5) ; v1@87.769,136.766 U8.19@87.769,138.704 ; U9.26@89.293,128.962 89.293,132.143 v1(89.738,132.588)
  Bottom Layer w0.254: v1(82.169,136.5) v1(87.503,136.5) 87.503,134.823 v1(89.738,132.588)
ADS1292_SPI_DOUT: 11.1 U8.21 U9.27 | length 29.7
  Top Layer w0.254: U9.27@88.793,128.962 88.793,134.074 88.769,134.098 U8.21@88.769,138.704 88.769,140.052 v1(89.535,140.818) ; v1(99.949,147.93) 99.949,149.2 11.1@101.981,151.232
  Bottom Layer w0.254: v1(89.535,140.818) 93.599,144.882 96.901,144.882 v1(99.949,147.93)
ADS1292_SPI_SCLK: 13.1 U8.20 U9.28 | length 21.9
  Top Layer w0.254: 13.1@81.864,147.32 82.626,146.558 84.15,146.558 v1(84.658,146.05) ; v1(87.757,140.31) 88.265,139.802 88.265,133.96 88.293,133.932 U9.28@88.293,128.962
  Bottom Layer w0.254: v1(84.658,146.05) 84.658,143.408 v1(87.757,140.31)
ADS1292_START: 15.1 U8.16 U9.30 | length 15.2
  Top Layer w0.254: 84.201,137.77 15.1@84.963,137.77 ; U8.16@85.369,140.103 84.483,140.103 84.201,139.821 84.201,138.204 84.201,134.722 84.963,133.96 86.741,133.96 87.292,133.408 U9.30@87.292,128.962
ADS1292_VCAP1: C55.1 U8.11 | length 4.6
  Top Layer w0.254: C55.1@80.791,142.603 U8.11@85.369,142.603
ADS1292_VCAP2: C56.1 U8.27 | length 6.8
  Top Layer w0.254: U8.27@91.669,141.103 93.467,141.103 95.02,139.55 95.02,138.022 95.527,137.516 C56.1@96.047,137.516
ADS1292_VREFP: C50.1 C51.1 U8.9 | length 5.9
  Top Layer w0.254: C51.1@81.651,145.58 C51.1@81.356,145.58 81.464,145.472 C50.1@82.88,145.472 83.712,145.472 83.896,145.288 83.896,144.018 84.311,143.603 U8.9@85.369,143.603
ADS_AVCC: C22.1 C23.1 C24.1 C39.1 C40.1 L6.2 R8.2 R24.2 R28.2 U2.5 U8.12 | length 21.4
  Top Layer w0.254: U2.5@76.119,143.8 77.074,143.8 77.292,144.018 v1(77.292,144.78) ; v1(76.53,145.542) 76.579,145.493 77.751,145.493 78.359,146.101 R8.2@78.359,147.33 ; v1(78.308,136.906) 78.672,137.27 79.525,137.27 C23.1@79.583,137.212 ; v1(78.901,141.106) C39.1@80.853,141.106 ; L6.2@79.629,135.522 79.629,137.166 C23.1@79.583,137.212 ; v1(80.645,148.184) C24.1@80.645,150.378 ; C22.1@80.853,137.212 C23.1@79.583,137.212 ; C39.1@81.153,141.164 C40.1@82.423,141.164 83.363,142.103 U8.12@85.369,142.103 ; v1(87.919,149.362) R28.2@87.919,150.932 R24.2@87.919,152.202
ADS_AVSS: C22.2 C23.2 C24.2 C39.2 C40.2 C44.2 C50.2 C51.2 C55.2 C56.2 C57.2 J3.10 J3.11 R3.2 R9.1 R12.1 R25.1 R29.1 U2.2 U3.2 U8.10 U8.13 | length 43.8
  Top Layer w0.254: v1(68.028,123.489) R3.2@69.844,123.489 ; v1(72.633,142.85) U2.2@73.719,142.85 ; R12.1@75.774,148.117 74.803,149.088 74.803,151.74 75.499,152.436 78.751,152.436 80.579,152.436 ; v1@77.851,143.612 v1(78.105,143.612) 78.105,143.205 78.715,142.596 C55.2@79.583,142.596 ; v1(79.832,146.304) 79.832,144.272 80.124,143.98 C51.2@81.356,143.98 81.648,144.272 C50.2@82.88,144.272 82.88,143.51 83.287,143.104 83.896,143.104 U8.10@85.369,143.103 ; C24.2@80.645,151.578 v1(80.645,153.518) ; C22.2@80.853,138.412 79.583,138.412 79.583,139.906 80.853,139.906 82.019,139.906 C40.2@82.25,140.137 ; C57.2@82.063,151.863 v1(82.063,153.496) ; C40.2@82.423,139.964 82.423,140.068 83.717,141.362 ; 83.717,141.373 83.947,141.603 U8.13@85.369,141.603 ; C44.2@86.385,151.891 v1(86.385,153.416) ; R29.1@91.913,150.932 R25.1@91.913,152.202 v1(91.913,153.426) ; C56.2@97.247,137.516 97.247,136.916 v1(97.663,136.5)
  Top Layer w0.54: v1(104.013,135.484) R9.1@104.013,137.17
  other v1: 79.883,139.906
ADS_DVCC: C15.1 C19.1 C20.1 C21.1 C41.1 C42.1 L5.2 L6.1 U8.23 | length 24.7
  Top Layer w0.254: L6.1@79.629,133.972 79.883,133.972 v1(79.883,132.436) ; 89.535,135.484 89.535,134.376 89.789,134.122 C42.1@90.551,134.122 C41.1@91.821,134.122 C19.1@93.091,134.122 C20.1@94.361,134.122 ; 89.551,135.5 90.297,136.246 90.297,137.008 89.769,137.536 U8.23@89.769,138.704 ; C20.1@94.389,134.15 C20.1@94.361,134.122 ; v1(95.326,133.858) 95.326,133.896 95.101,134.122 C20.1@94.361,134.122 ; v1(97.663,132.944) C21.1@97.663,134.122 98.333,133.452 L5.2@99.657,133.452 99.657,134.176 100.711,135.23 100.711,139.294 99.949,140.056 C15.1@99.949,141.296
ANTENNA: D1.2 D2.2 R13.2 R14.2 | length 600.2
  Top Layer w0.4: v1(77.089,95.86) 77.851,96.622 98.679,96.622 98.679,73 76.327,73 76.327,97.13 99.187,97.13 99.187,72.492 75.819,72.492 75.819,97.638 99.695,97.638 99.695,71.984 75.26,71.984 75.26,98.044 76.073,98.857 76.073,103.631 76.629,104.055 77.72,104.055 ; v1(77.089,100.178) 77.089,101.702 77.699,102.311 84.455,102.311 84.785,102.641 D2.2@84.785,103.239 ; D1.2@77.72,106.379 77.72,104.055 ; R13.2@79.498,104.055 77.72,104.055 ; 81.022,102.311 R14.2@81.022,104.055
  Bottom Layer w0.4: 75.26,97.079 75.26,71.984 99.695,71.984 99.695,97.638 77.089,97.638 v1(77.089,100.178) ; 75.311,97.13 99.187,97.13 99.187,72.492 75.819,72.492 75.819,96.622 98.679,96.622 98.679,73 76.327,73 76.327,95.098 v1(77.089,95.86)
BMA_AVCC: C16.1 C37.1 L4.1 U6.7 | length 5.4
  Top Layer w0.254: C16.1@74.041,128.647 C37.1@75.311,128.647 ; U6.7@75.044,127.111 75.044,128.38 C37.1@75.311,128.647 ; L4.1@76.797,129.896 76.797,129.045 76.557,128.805 75.47,128.805 C37.1@75.311,128.647
BMA_DVCC: C17.1 C36.1 L3.2 L4.2 U6.1 U6.3 U6.11 | length 28.6
  Top Layer w0.254: U6.11@75.569,125.586 75.569,124.794 75.286,124.511 73.939,124.511 72.669,125.781 72.669,129.616 74.168,131.115 78.029,131.115 78.397,130.747 L4.2@78.397,129.896 78.397,129.096 79.375,128.118 L3.2@80.353,128.118 80.391,128.08 C17.1@80.391,126.224 C36.1@79.121,126.224 78.734,126.611 U6.3@76.594,126.611 ; U6.1@76.594,125.611 76.594,125.158 77.038,124.714 77.902,124.714 78.384,125.197 78.384,126.585
BMA_INT1: U6.5 U9.38 | length 11
  Top Layer w0.254: U6.5@76.069,127.136 76.069,127.657 76.204,127.792 v1(76.68,127.792) ; v1(82.169,126.848) 83.185,125.832 ; 83.205,125.812 U9.38@85.643,125.812
  Bottom Layer w0.254: v1(76.68,127.792) 77.648,127.792 78.667,126.774 79.212,126.774 79.286,126.848 v1(82.169,126.848)
BMA_INT2: U6.6 U9.33 | length 12.2
  Top Layer w0.254: U6.6@75.569,127.136 75.569,127.88 76.141,128.451 77.216,128.451 77.543,128.778 v1(77.622,128.778) ; v1(83.896,129.286) 83.896,128.676 84.261,128.312 U9.33@85.643,128.312
  Bottom Layer w0.254: v1(77.622,128.778) 83.388,128.778 v1(83.896,129.286)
